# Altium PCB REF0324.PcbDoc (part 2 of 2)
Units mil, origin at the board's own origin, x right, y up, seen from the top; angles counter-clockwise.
Board outline 2010 x 1686 mil, 4 copper layers (Top Layer, Signal Layer 1, Signal Layer 2, Bottom Layer), stack 61.2 mil thick; 109 components, 70 nets, 426 pads, 300 vias.
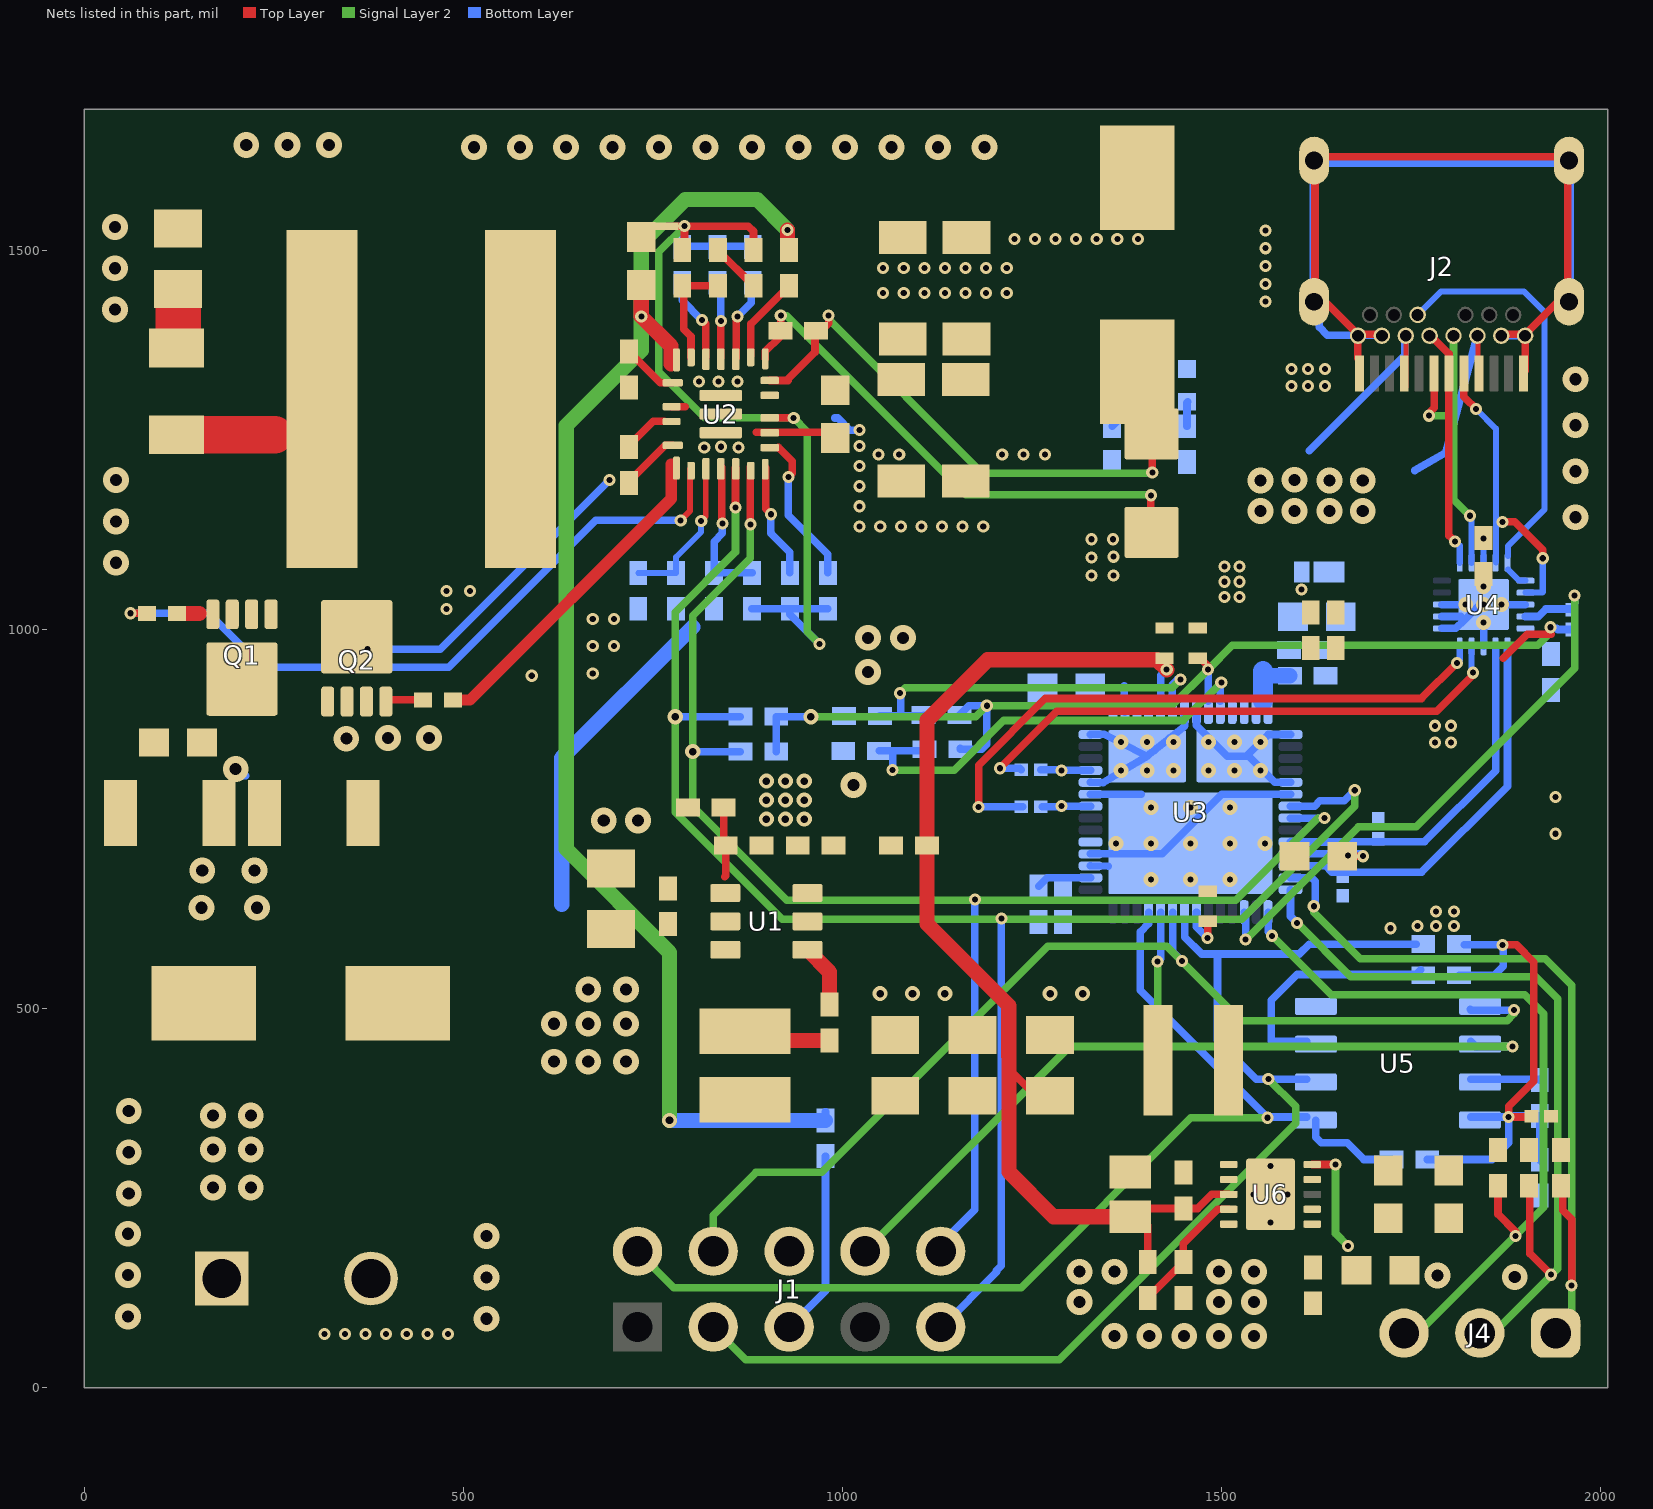
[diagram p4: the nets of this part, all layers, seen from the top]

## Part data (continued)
R20: library part CMP-0025950-3, "RES, 100 k, 1%, 0.063 W, AEC-Q200 Grade 0, 0402", Manufacturer=Vishay-Dale, Power_W=63mW, Supplier Part Number 1=541-100KLCT-ND, TempCo="100 ppm/C", Tolerance_%=1%, Value2=0.063W, Value_Code=133k
R21: library part CMP-0026178-2, "RES, 22.1 k, 1%, 0.063 W, AEC-Q200 Grade 0, 0402", Manufacturer=Vishay-Dale, Power_W=63mW, Supplier Part Number 1=541-22.1KLCT-ND, TempCo="100 ppm/C", Tolerance_%=1%, Value2=0.063W, Value_Code=22k1, ValueDisplayed=22.1k
R22 R23: library part CMP-0026339-2, "RES, 3.83 k, 1%, 0.063 W, AEC-Q200 Grade 0, 0402", Manufacturer=Vishay-Dale, Power_W=63mW, Supplier Part Number 1=541-3.83KLCT-ND, TempCo="100 ppm/C", Tolerance_%=1%, Value2=0.063W, Value_Code=3k83, ValueDisplayed=3.83k
R24 R31 R32: library part CMP-0027008-4, "RES, 0, 5%, 0.05 W, 0201", Manufacturer=Vishay-Dale, Power_W=50mW, Supplier Part Number 1=72M6743, TempCo=ppm/C, Tolerance_%=5%, Value2=0.05W, Value_Code=0000, ValueDisplayed=0
R25: library part CMP-0025950-3, "RES, 100 k, 1%, 0.063 W, AEC-Q200 Grade 0, 0402", Manufacturer=Vishay-Dale, Power_W=63mW, Supplier Part Number 1=541-100KLCT-ND, TempCo="100 ppm/C", Tolerance_%=1%, Value2=0.063W, Value_Code=220k
R26 R37 R38 R46: library part CMP-0026658-1, "RES, 10.0 k, 1%, 0.1 W, 0402", Manufacturer=Panasonic, Power_W=100mW, Supplier Part Number 1=P10.0KLCT-ND, TempCo="100 ppm/C", Tolerance_%=1%, Value2=0.1W, Value_Code=10k0, ValueDisplayed=10.0k
R27: library part CMP-0026359-2, "RES, 3.48, 1%, 0.063 W, AEC-Q200 Grade 0, 0402", Manufacturer=Vishay-Dale, Power_W=63mW, Supplier Part Number 1=541-3.48LLCT-ND, TempCo="100 ppm/C", Tolerance_%=1%, Value2=0.063W, Value_Code=3R48, ValueDisplayed=3.48
R28 R34 R40 R41: library part CMP-0025950-3, "RES, 100 k, 1%, 0.063 W, AEC-Q200 Grade 0, 0402", Manufacturer=Vishay-Dale, Power_W=63mW, Supplier Part Number 1=541-100KLCT-ND, TempCo="100 ppm/C", Tolerance_%=1%, Value2=0.063W, Value_Code=100k
R35: library part CMP-0027184-1, "RES, 100 k, 5%, 0.05 W, 0201", Manufacturer="Yageo America", Power_W=50mW, Supplier Part Number 1=603-RC0201JR-7D100KL, TempCo="200 ppm/C", Tolerance_%=5%, Value2=0.05W, Value_Code=100k
R48 R49 R50 R51: library part CMP-0026918-5, "RES, 3.3 k, 5%, 0.063 W, AEC-Q200 Grade 0, 0402", Manufacturer=Vishay-Dale, Power_W=63mW, Supplier Part Number 1=541-3.3KJCT-ND, TempCo="200 ppm/C", Tolerance_%=5%, Value2=0.063W, Value_Code=3k30, ValueDisplayed=3.3k
U1: library part CMP-0065101-3, "4V to 36 V 0.6 A Synchronous Step-Down Converter, DBV0006A (SOT-23-6)", Alternate Manufacturer="Texas Instruments", Alternate PartNumber=TPS560430YDBVT
U2: library part CMP-0085347-3, "36-V, 16-A Buck-Boost Converter, RPM0026A (VQFN-HR-26)", Alternate Manufacturer="Texas Instruments"
U3: library part CMP-0081032-2, "USB Type-C and USB PD Controller with Integrated Power Switches, RSH0056E (VQFN-56)", Alternate Manufacturer="Texas Instruments", Alternate PartNumber=TPS65987DDHRSHT
U4: library part CMP-0081565-1, "USB Type-C Port Protector: Short-to-VBUS Overvoltage and IEC ESD Protection, RUK0020B (WQFN-20)", Alternate Manufacturer="Texas Instruments"
U5: library part CMP-0078948-1, "8Mb, 86MHz, NOR Flash, SOP-8", Manufacturer="Macronix International Co., LTD", Supplier Part Number 1=1092-1117-ND
U6: library part CMP-0034518-5, "Integrated USB Power Switch with Boost Converter, DRC0010J (VSON-10)", Continuous Current(Max)(A)=1.4, Current Limit(A)="0.13 to 1.4", Current Limit Topology=Constant-Current, Manufacturer="Texas Instruments", Operating Temperature Range="-40 to 85 C", Rating=0

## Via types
v1: diameter 16, hole 8, Top Layer to Bottom Layer, tented both sides, 164 vias
v2: diameter 34, hole 16, Top Layer to Bottom Layer, tented both sides, 84 vias
v3: diameter 19.68, hole 7.87, Top Layer to Bottom Layer, 34 vias
v4: diameter 20, hole 10, Top Layer to Bottom Layer, tented both sides, 18 vias

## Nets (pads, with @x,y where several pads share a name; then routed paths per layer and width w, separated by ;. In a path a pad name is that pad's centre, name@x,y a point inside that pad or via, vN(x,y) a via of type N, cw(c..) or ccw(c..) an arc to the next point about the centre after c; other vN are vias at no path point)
/FLT_TPD: R35.1 U3.31 U4.9 | length 795.5
  Signal Layer 2 w10: v1@1530,593 v1(1532,591) 1681,740 1757,740 1966,949 v1(1966,1045)
  Bottom Layer w10: U3.31@1530.24,627.22 1530,626.98 1532,624.98 1530,622.98 1532,620.98 v1(1532,591) ; U4.9@1901.12,1017.13 1918.13,1017.13 1928,1027 1960.99,1027 R35.1@1962,1025.99 ; R35.1@1966,1034.8 v1(1966,1045)
ADCIN1: R37.1 R40.2 U3.6 | length 499
  Signal Layer 2 w10: v1(1076,916) 1083.02,923.02 1435.02,923.02 v1(1446,934)
  Bottom Layer w10: R40.2@1049.62,886 1077,886 ; v1@1077,914 1077,886 ; R37.1@1107.38,887 1106.38,886 1077,886 ; U3.6@1435.39,905.35 1435.39,927.39 1442,934 v1(1446,934)
ADCIN2: R38.1 R41.2 U3.10 | length 594.2
  Signal Layer 2 w10: v1(1066.5,814.5) 1147.5,814.5 1213,880 1450,880 v1(1500,930)
  Bottom Layer w10: R41.2@1048.62,840 1070,840 ; v1(1066.5,814.5) 1066.5,836.5 1070,840 ; R38.1@1108.38,842 1106.38,840 1070,840 ; U3.10@1498.39,905.35 1498.39,928.39 v1(1500,930)
AGND: C18.2 C19.2 C20.2 NT1.2 R7.1 R14.1 R15.1 R16.1 R17.1 U2.10 | length 1212.7
  Top Layer w10: NT1.2@769,1532 v1(792,1532) ; C18.2@789,1500.62 792,1503.62 v1(792,1532) ; C20.2@883,1500.62 883,1525 876,1532 v1(792,1532) ; U2.10@898,1279.04 v1(936,1279.04)
  Signal Layer 2 w10: v1(792,1532) 758,1498 758,1340 818.96,1279.04 v1(936,1279.04) 954,1261.04 954,997 v1(970,981)
  Bottom Layer w10: R17.1@791,1504.62 R17.1@791,1505.24 ; v1(792,1532) 791,1531 R17.1@791,1505.24 ; R15.1@880,1505.24 R17.1@791,1505.24 ; R7.1@881,1027.38 C19.2@931,1027.38 ; v1(970,981) 931,1020 C19.2@931,1027.38 ; R14.1@981,1027.38 C19.2@931,1027.38
C_CC1: J2.A5 U4.4 U4.7 | length 425.1
  Top Layer w10: J2.A5@1819.95,1339.69 1819.95,1306.98 v1@1838,1288.93 ; v1(1871,1142) 1887,1142 1924,1105 v1(1924,1094)
  Bottom Layer w8: v1(1835.93,1291) 1862.05,1264.88 U4.4@1862.05,1088.3 ; U4.7@1901.12,1048.63 1923.37,1048.63 ; 1924,1049.26 v1(1924,1094)
  Bottom Layer w10: v1@1864,1142 v1(1871,1142)
C_CC2: J2.B5 U4.5 U4.6 | length 561.6
  Bottom Layer w8: J2.B5@1759,1415 1790,1446 1899,1446 1926,1419 1926,1158 1878,1110 U4.5@1878,1097 ; U4.5@1878.5,1079 1893.12,1064.38 U4.6@1901.12,1064.38
C_USB_N: J2.A7 J2.B7 U4.2 | length 413.2
  Top Layer w10: v1(1774,1282) 1774,1286 1780.65,1292.65 J2.A7@1780.65,1337.84
  Signal Layer 2 w10: v1(1774,1282) 1806.24,1282 1806.24,1295 ; J2.B7@1806.24,1387.44 1806.24,1295 ; v1(1828,1150) 1806.24,1171.76 1806.24,1295
  Bottom Layer w8: v1(1828,1150) 1830.25,1147.75 U4.2@1830.25,1088
C_USB_P: J2.A6 J2.B6 U4.1 | length 323.6
  Top Layer w10: J2.B6@1774.75,1387.44 1776.52,1387.44 1800,1363.97 ; J2.A6@1800.53,1349.39 1800.53,1363.43 1800,1363.97 ; v1(1808,1116) 1800,1124 1800,1363.97
  Bottom Layer w8: U4.1@1814.5,1088 1814.5,1110.5
CC1: C36.1 U3.24 U4.12 | length 473.3
  Bottom Layer w10: U3.24@1591.27,719.74 1657,719.74 ; 1657,720 1768,720 1861.75,813.75 U4.12@1861.75,977.76
CC2: C37.1 U3.26 U4.11 | length 520.9
  Bottom Layer w10: U3.26@1591.27,688.24 1637.75,688.24 1645.99,680 1764,680 1877.5,793.5 U4.11@1877.5,977.76
DRAIN1: U3.8 U3.15 U3.19 U3.58@1517.45,832.93 | length 242.3
  Bottom Layer w10: U3.8@1467.25,891 1467.25,873.75 1508.07,832.93 1536.07,832.93 1570.52,798.48 U3.19@1591.27,798.48 ; U3.58@1533.2,832.93 1561.74,861.47 U3.15@1591.27,861.47
  other v3: 1483,814.23 1517.45,814.23 1551.9,814.23 1483,851.63 1517.45,851.63 1551.9,851.63
DRAIN2: U3.7 U3.52 U3.56 U3.57@1402.29,832.93 | length 248.1
  Bottom Layer w10: U3.52@1327.49,798.48 1344,798 1368.7,812.8 U3.57@1402.29,832.93 ; U3.56@1327.49,861.47 1345,862 1367.35,850.66 U3.57@1402.29,832.93 ; U3.7@1451.5,891 1452,873 1432.31,857.13 1411.43,840.3 U3.57@1402.29,832.93
  other v3: 1367.84,814.23 1402.29,814.23 1436.74,814.23 1367.84,851.63 1402.29,851.63 1436.74,851.63
GND: C1.2 C2.2 C3.2 C4.2 C5.2 C6.2 C9.2 C10.2 C12.2 C13.2 C14.2 C15.2 C16.2 C17.2 C21.2 C22.2 C23.2 C25.2 C26.2 C27.2 C28.2 C29.2 C30.2 C32.2 C33.2 C34.2 C35.2 C36.2 C37.2 C38.2 C39.2 C40.2 C41.2 C42.2 C43.2 C44.2 C45.2 C46.2 C47.2 D1.2 D3.2 J1.6 J2.A1 J2.A12 J2.B1 J2.B12 J2.M1 J2.M2 J2.S1 J2.S2 J2.S3 J2.S4 J3.2 NT1.1 Q2.1 Q2.2 Q2.3 R5.1 R20.1 R21.1 R27.1 R28.1 R34.1 R40.1 R41.1 U1.2 U2.9 U2.24 U3.20 U3.45 U3.46 U3.47 U3.51 U3.59@1459.38,717.77 U4.8 U4.13 U4.16 U4.17 U4.18 U4.21@1846,1032.88 U5.4 U6.2 U6.5 U6.11 | length 2557.6
  Top Layer w10: 887,1260 983.5,1260 C12.2@991,1252.5 ; J2.S3@1623.53,1623.94 1623.53,1437.72 1631.76,1437.72 J2.B1@1680.19,1389.29 ; J2.S3@1629.99,1623.78 J2.S2@1948.53,1623.78 ; J2.A12@1680.19,1357.8 J2.B1@1680.19,1389.29 ; J2.M1@1711.68,1389.29 J2.B1@1680.19,1389.29 ; J2.M2@1869.16,1389.29 J2.B12@1900.66,1389.29 ; J2.A1@1898.69,1339.69 1900.66,1341.65 J2.B12@1900.66,1389.29 ; J2.S2@1956.92,1618.94 J2.S1@1956.92,1434.17 ; J2.S1@1958.53,1434.17 J2.S1@1956.92,1434.17 ; J2.B12@1900.66,1389.29 1945.54,1434.17 J2.S1@1956.92,1434.17
  Bottom Layer w10: 990,1279 994,1279 1010,1263 v1(1023,1263) ; U3.45@1327.49,688.24 1351,688 ; U3.46@1327.49,703.99 1422.02,704.02 1500.73,782.73 U3.20@1591.27,782.73 ; U3.51@1327.49,782.73 U3.59@1394.42,782.73 ; J2.S4@1621,1428.78 1621,1615 1960,1615 J2.S1@1960,1428.78 ; J2.S4@1629,1411 1629,1399 1640,1388 J2.M1@1711.76,1388 ; U4.16@1790.88,1001.39 1809.39,1001.39 U4.21@1820.5,1012.5 ; U4.17@1790.88,1017.13 1815.87,1017.13 U4.21@1820.5,1012.5 ; U4.18@1790.88,1032.88 v3(1822.38,1032.88) ; U4.13@1846,977.76 v3(1846,1009.26) ; v3(1846,1032.88) 1840.88,1032.88 U4.21@1820.5,1012.5 ; J2.M2@1869.24,1387.44 J2.B12@1900.73,1387.44 ; v3(1869.62,1032.88) U4.8@1901.12,1032.88
  other v1: 317,71 344.17,71 371.33,71 398.5,71 425.67,71 452.83,71 480,71 1723,606 1941,730.65 1941,779 1782,851 1803,851 1782,873 1803,873 590.5,939 671,942 671,978 699,978 671,1014 699,1014 478,1027 478,1051 509,1051 1023,1136 1050.17,1136 1077.33,1136 1104.5,1136 1131.67,1136 1158.83,1136 1186,1136 1023,1162.5 1023,1189 1023,1215.5 1048,1231 1075.17,1231 1211,1231 1239.25,1231 1267.5,1231 818,1240 863,1240 840,1241 1023,1242 1592.53,1321.39 1614.53,1321.39 1636.53,1321.39 1592.53,1343.39 1614.53,1343.39 1636.53,1343.39 1558.53,1432.39 1054,1444 1081.17,1444 1108.33,1444 1135.5,1444 1162.67,1444 1189.83,1444 1217,1444 1558.53,1455.89 1054,1477 1081.17,1477 1108.33,1477 1135.5,1477 1162.67,1477 1189.83,1477 1217,1477 1558.53,1479.39 1558.53,1502.89 1227,1515 1254.17,1515 1281.33,1515 1308.5,1515 1335.67,1515 1362.83,1515 1390,1515 1558.53,1526.39
  other v2: 1359,68 1405,68 1451,68 1497,68 1543,68 531,91 58,94 1313,113 1497,113 1543,113 531,145.5 1887,146 1785,148 58,148.5 1313,153 1359,153 1497,153 1543,153 531,200 58,203 59,256 59,310.5 59,365 685.5,748 730.5,748 1015,795 346,856 401,857 455,857 1034,944 1034,989 1080,989 42,1088 42,1142.5 1967,1148 42,1197 1967,1208.67 1967,1269.33 1967,1330 41,1422 41,1476.5 41,1531 514.5,1636 575.17,1636 635.83,1636 697.13,1636 758.43,1636 819.72,1636 881.02,1636 942.31,1636 1003.61,1636 1064.91,1636 1126.2,1636 1187.5,1636 214,1639 268.5,1639 323,1639
  other v3: 1564.88,217.6 1542.24,255 1587.52,255 1564.88,292.4 1407.41,670.53 1459.38,670.53 1511.35,670.53 1360.95,717.77 1407.41,717.77 1459.38,717.77 1511.35,717.77 1557.8,717.77 1407.41,765.02 1459.38,765.02 1511.35,765.02 1846,1009.26 1846,1056.5 1846,1056.5
  other v4: 1050,519.7 1092.75,519.7 1135.5,519.7 1274.25,519.7 1317,519.7 900,750 925,750 950,750 900,775 925,775 950,775 900,800 925,800 950,800
I2C1_IRQ: J4.3 R26.1 U3.29 | length 1015.7
  Top Layer w10: R26.1@1865,264.38 1865,229 1888,206 v1(1888,200)
  Signal Layer 2 w10: v1(1567,596) 1645,518 1900,518 1925,493 1925,238 1759,72 J4.3@1741,72
  Bottom Layer w10: U3.29@1561.74,627.22 1561.74,601.26 v1(1567,596)
I2C1_SCL: J4.1 R22.1 U3.27 | length 1062.6
  Top Layer w10: R22.1@1950.29,254.66 1950.29,234 1962,222.29 v1(1962,135)
  Signal Layer 2 w10: v1(1622,635) 1622,627 1683,566 1927,566 1962,531 1962,139 1959.29,136.29 1960.57,135 v1(1962,135) 1962,94.43 1959.29,91.71 1969,82 J4.1@1951,64
  Bottom Layer w10: U3.27@1591.27,672.5 1619.5,672.5 1624,668 v1@1624,635
I2C1_SDA: J4.2 R23.1 U3.28 | length 1056
  Top Layer w10: R23.1@1907,266.38 1907,177 v1(1935,149)
  Signal Layer 2 w10: v1(1600,613) 1671,542 1915,542 1944,513 1944,157 1859,72 J4.2@1841,72
  Bottom Layer w10: U3.28@1591.27,656.75 1591.27,621.73 v1(1600,613)
I2C3_SCL: J1.9 R9.1 U2.5 U3.21 | length 2277.2
  Top Layer w10: v1(859.22,1160.71) U2.5@859.22,1213.05
  Signal Layer 2 w10: v1(859.22,1160.71) 859.22,1102.22 779.85,1022.85 v4(779.85,885) 779.85,758.9 920.75,618 1527,618 1676,767 v1(1676,788)
  Bottom Layer w10: v4(779.85,885) R9.1@865.76,885 ; J1.9@1130,80 1131,80 1204,153 1203,154 1210,161 v1(1210,619) ; U3.21@1591.27,766.98 1622.98,766.98 1630,774 1662,774 v1(1676,788)
I2C3_SDA: J1.10 R10.1 U2.6 U3.22 | length 1998.9
  Top Layer w10: v1(878.9,1138.76) U2.6@878.9,1214.59
  Signal Layer 2 w10: v4@801.88,838 v4(802.88,839) ; v4@803,838 803,767 927,643 1519,643 1627.24,751.24 v1(1636,751.24) ; v4@803,839 803,1018 878.9,1093.9 v1(878.9,1138.76)
  Bottom Layer w10: v4(802.88,839) R10.1@865.76,839 ; J1.10@1130,180 1130,190 1175,235 v1(1175,644) ; U3.22@1591.27,751.24 v1(1636,751.24)
LDO_3V3: C39.1 C45.1 R9.2 R10.2 R22.2 R23.2 R24.1 R26.2 R35.2 R37.2 R38.2 U3.9 U4.10 | length 1411.1
  Top Layer w10: C45.1@1470.5,963.5 1482.64,951.36 v1(1482.64,947.24) ; 1872,962 1903.62,993.62 1935,993.62
  Signal Layer 2 w10: v4(958.74,885) 1176.29,885 v1(1190.71,899.42) 1434.81,899.42 v1(1482.64,947.24) 1514.39,979 1917.16,979 1934,995.84 v1(1934,1003)
  Bottom Layer w10: R10.2@913,839 R9.2@913,885 v4(958.74,885) ; R37.2@1154.62,887 1167.04,899.42 v1(1190.71,899.42) 1190.71,848.71 1184,842 R38.2@1155.62,842 R38.2@1155.62,843.38 ; U3.9@1482.64,905.35 v1(1482.64,947.24) ; 1942.16,1001.84 1943.99,1000.01 R35.2@1962,1000.01
NetC5_1: C5.1 R1.1 | length 58
  Top Layer w60: R1.1@124,1385 C5.1@124,1443
NetC6_1: C6.1 R34.2 U3.44 | length 73.1
  Bottom Layer w10: R34.2@1259,661.24 1270.25,672.5 U3.44@1327.49,672.5
NetC7_1: C7.1 U2.22 | length 51.4
  Top Layer w10: C7.1@724.5,1248.5 750.74,1274.74 U2.22@765.04,1274.74
NetC7_2: C7.2 L1.1 Q1.1 Q1.2 Q1.3 Q2.5 Q2.6 Q2.7 Q2.8 Q2.9@359.67,990.38 R1.2 U2.23 | length 628.9
  Top Layer w10: 251.09,1256.91 262,1246 ; C7.2@722,1198 766.82,1242.82 U2.23@776.48,1242.82
  Top Layer w50: R1.2@122,1256.91 251.09,1256.91
  Bottom Layer w10: v1(374,974) 470,974 v1(693,1197)
NetC8_1: C8.1 U2.20 | length 74.5
  Top Layer w10: C8.1@719,1366.62 760.13,1325.5 U2.20@776.48,1325.5
NetC8_2: C8.2 L1.2 U2.21 U2.25 | length 18
  Top Layer w10: U2.21@775,1294 793,1294
NetC9_1: C9.1 R6.1 U2.3 | length 205.6
  Top Layer w7.87: v1(814,1143) 820,1149 U2.3@820,1214.05
  Bottom Layer w7.87: C9.1@731,1074.62 R6.1@781,1074.62 781,1095.56 814,1128.56 v1(814,1143)
NetC10_1: C10.1 C11.1 C12.1 C13.1 C14.1 C15.1 C16.1 R8.1 U2.11 U2.12 U2.26 | length 700.9
  Top Layer w10: U2.12@904.43,1328.45 928.45,1328.45 929,1329 929,1330.86 964.07,1365.93 964.07,1385.93 982,1403.86 v1(982,1414) ; R8.1@1407.16,1260.73 1409,1258.89 v1(1409,1207)
  Signal Layer 2 w10: v1(982,1414) 982,1408.93 1184.93,1206 v1@1407.53,1206
  other v1: 811.35,1327 836.63,1327 861.91,1327
NetC18_1: C18.1 R12.2 U2.18 | length 146.2
  Top Layer w10: U2.18@800.59,1358.96 800.59,1386.41 791,1396 791,1451.38 C18.1@789,1453.38 R12.2@836,1453.38
NetC19_1: C19.1 U2.7 | length 152.2
  Top Layer w10: U2.7@899,1213.56 899,1159 v1(906,1152)
  Bottom Layer w10: v1(906,1152) 906,1127 907,1126 907,1125.93 931,1101.93 C19.1@931,1074.62
NetC20_1: C20.1 R12.1 | length 66.7
  Top Layer w10: R12.1@836,1500.62 836,1500.38 C20.1@883,1453.38
NetC24_1: C24.1 U1.1 | length 84.4
  Top Layer w20: U1.1@954.13,577.6 983.37,548.37 C24.1@983.37,505.26
NetC24_2: C24.2 L2.1 U1.6 | length 116.4
  Top Layer w20: L2.1@871.92,470.08 883.98,458.02 C24.2@983.37,458.02
NetC27_1: C27.1 U3.35 | length 62.3
  Top Layer w10: v1(1482,593) C27.1@1482,615
  Bottom Layer w10: U3.35@1467.25,627.22 1467.25,607.75 v1(1482,593)
NetC28_1: C28.1 U6.7 U6.10 | length 144.8
  Top Layer w10: U6.10@1620,294.37 1650.27,294.37 v1@1650.64,294
  Signal Layer 2 w10: v1(1650.64,294.24) 1650.64,203.36 v1(1667,187)
NetC31_2: C31.2 R27.2 | length 45.9
  Bottom Layer w10: R27.2@1356,1268.14 C31.2@1388.43,1300.56
NetC40_1: C40.1 U4.3 | length 32
  Bottom Layer w8: U4.3@1846,1088 v1(1846,1120)
NetC43_1: C43.1 R24.2 R48.2 R49.2 R50.2 R51.2 U5.8 | length 744.8
  Top Layer w10: v1(1871,584) 1889.35,584 1912,561.35 1912,404 1878.92,370.92 v1(1878.92,357) 1908.01,357 R24.2@1909.01,358
  Bottom Layer w10: R48.2@1771.62,301 1857,301 1878.92,322.92 v1(1878.92,357) ; R51.2@1813.62,544 1860,544 1872,556 1872,583 v1(1871,584) R49.2@1820.62,584 ; U5.8@1829.27,357 v1(1878.92,357) ; C43.1@1921,299.62 C43.1@1920,300.62 R50.2@1920,358.38 1877.54,358.38 v1(1878.92,357)
NetD3_1: D3.1 R46.1 | length 32.7
  Bottom Layer w10: R46.1@1454.75,1268.14 1454.75,1299.1 D3.1@1456,1300.35
NetJ1_5: J1.5 R13.1 | length 245.3
  Bottom Layer w10: J1.5@930,80 978,128 R13.1@978,305.38
NetL3_2: L3.2 U6.1
NetQ1_4: Q1.4 R3.2 | length 29.3
  Top Layer w20: R3.2@122.69,1021 152,1021
NetQ2_4: Q2.4 R4.2 | length 56
  Top Layer w10: Q2.4@398.06,904.94 400.45,907.34 R4.2@447,907.34 ; R4.2@447,907.31 R4.2@447.31,907 ; R4.2@447.31,907.34 R4.2@452.9,907.34
NetR2_1: R2.1 R7.2 U2.4 | length 194.4
  Top Layer w10: U2.4@841,1214.05 841,1141 v1(842,1140)
  Bottom Layer w10: v1(842,1140) 842,1127 831,1116 R2.1@831,1074.62 R7.2@881,1074.62
NetR3_1: R3.1 U2.2 | length 933.3
  Top Layer w7.87: v1(787,1144) 799,1156 U2.2@799,1211.59
  Top Layer w10: v1(61.53,1021.39) R3.1@86.85,1021.39
  Bottom Layer w10: v1(61.53,1021.39) 164.61,1021.39 236,950 481,950 675,1144 v1(787,1144)
NetR4_1: R4.1 U2.1 | length 443.5
  Top Layer w15: R4.1@486.69,907 509,907 774.51,1172.51 774.51,1218.21
NetR5_2: R5.2 U6.6
NetR11_2: R11.2 U2.14 | length 113.1
  Top Layer w10: U2.14@879.53,1361.2 879.53,1402.91 R11.2@930,1453.38
NetR14_2: R14.2 U2.8 | length 196.4
  Top Layer w10: U2.8@916,1240 934,1222 934,1206 v1(929,1201)
  Bottom Layer w10: v1(929,1201) 929,1150.93 981,1098.93 R14.2@981,1074.62
NetR15_2: R15.2 U2.15 | length 107.8
  Top Layer w10: U2.15@860,1358.74 860,1411 v1(862,1413)
  Bottom Layer w10: v1(862,1413) 880,1431 880,1455.38 R15.2@882,1457.38
NetR16_2: R16.2 U2.16 | length 85.3
  Top Layer w10: U2.16@840,1358.74 v1(840,1407)
  Bottom Layer w10: v1(840,1407) R16.2@840,1444
NetR17_2: R17.2 U2.17 | length 110.9
  Top Layer w10: v1(815,1408) 820,1403 U2.17@820,1359.34
  Bottom Layer w10: R17.2@789,1457.38 789,1434 v1(815,1408)
NetR18_1: R18.1 R20.2 U1.4 | length 87.7
  Top Layer w10: R18.1@843.62,760 843.62,717.76 R20.2@846.38,715 846.38,675.38 845,674
NetR19_1: R19.1 R21.2 U1.3
NetR25_1: R25.1 R28.2 U6.4 | length 169.6
  Top Layer w10: R25.1@1403,118.38 1450,165.38 R28.2@1450,165.62 1450,190 1495.32,235.32 U6.4@1509.76,235.32
NetR31_2: R31.2 U3.50 | length 63.9
  Bottom Layer w10: R31.2@1263.99,766 1288.03,766 v1(1289.02,766.98) U3.50@1327.49,766.98
NetR32_2: R32.2 U3.53 | length 66
  Bottom Layer w10: R32.2@1261.99,815 1288,815 v1(1289,814) 1289.23,814.23 U3.53@1327.49,814.23
NetR50_1: R50.1 U5.7 | length 91.3
  Bottom Layer w10: U5.7@1829.27,407 1918.62,407 R50.1@1920,405.62
NetR51_1: R51.1 U5.3 | length 314.3
  Bottom Layer w10: U5.3@1612.73,457 1566,457 1566,511 1600,545 1757,545 R51.1@1763,551
P_3V3: C22.1 C25.1 C26.1 C42.1 C46.1 C47.1 L2.2 L3.1 R19.2 R25.2 U3.5 U6.3 | length 1478.7
  Top Layer w10: 1220,420 C46.1@1264.47,375.53 ; C25.1@1380,236.38 C26.1@1450,236.38 1469.02,236.38 1487.64,255 U6.3@1509.76,255 ; R25.2@1403,165.62 C25.1@1403,214
  Top Layer w20: C25.1@1380,225.47 1278.89,225.47 1220,284.36 1220,420 1219.75,450 1219.75,503.79 1111.62,611.92 R19.2@1111.62,715 1111.62,880.2 1191.42,960 1415,960 v1(1428,947)
  Bottom Layer w10: U3.5@1420.39,900 1420.39,939.39 v1(1428,947)
P_5V: C29.1 C30.1 C38.1 U3.25 U6.9 | length 125.9
  Top Layer w10: C38.1@1659.5,701 v1(1687,701)
  Bottom Layer w10: U3.25@1591.27,703.99 1684.01,703.99 v1(1687,701) ; v1@1806,608 v1(1807,609)
  other v1: 1759,609 1783,609 1783,628 1807,628 1667,702
PP_HV: C11.2 C44.1 R8.2 U2.13 U3.1 U3.2 U3.11 U3.12 | length 715.2
  Top Layer w10: U2.13@898.52,1356.99 898.52,1366.9 C11.2@917.31,1385.69 ; C11.2@918.38,1394 919,1394.62 v1(919,1414) ; R8.2@1407.16,1139.81 v1(1407.16,1177)
  Signal Layer 2 w10: v1(919,1414) 926.93,1414 1162.93,1178 v1@1407.53,1178
  Bottom Layer w10: 1372,926 U3.2@1372.76,891
  other v1: 1504,1043 1524,1043 1504,1063 1524,1063 1329,1071 1358,1071 1504,1083 1524,1083 1329,1095 1358,1096 1329,1119 1357,1119
SPI_CLK: J1.8 U3.38 U5.6 | length 1205.2
  Signal Layer 2 w10: J1.8@1030,180 1300,450 v1(1884,450) ; 1416,456 v1(1416,562)
  Bottom Layer w10: J1.8@1030,180 J1.8@1038,180 ; v1(1416,562) 1420.01,566.01 U3.38@1420.01,627.22 ; U5.6@1829.27,457 1837.27,449 1838.27,450 v1(1884,450)
SPI_CSZ: J1.2 R48.1 U3.39 U5.1 | length 1475.8
  Signal Layer 2 w10: J1.2@730,180 778,132 1236,132 1460,356 v1(1561,356)
  Bottom Layer w10: U3.39@1404.26,627.22 1404.26,612.26 1393,601 1393,524 v1(1561,356) 1562,357 U5.1@1612.73,357 ; U5.1@1624.73,353 1624.73,330.27 1632,323 1666,323 1688,301 R48.1@1724.38,301
SPI_MISO: J1.3 R49.1 U3.36 U5.2 | length 1578.7
  Signal Layer 2 w10: J1.3@830,80 873,37 1286,37 1598,349 1598,371 v1(1562,407)
  Bottom Layer w10: U3.36@1452,617 1452,594 1474,572 1603,572 1616,585 R49.1@1757.38,585 ; 1495,567 1495,458 1546,407 v1(1562,407) U5.2@1612.73,407
SPI_MOSI: J1.4 U3.37 U5.5 | length 1427.2
  Signal Layer 2 w10: J1.4@830,180 830,227.68 886.32,284 973.15,284 1271.15,582 1428,582 1526,484 1877,484 1886,493 v1(1886,498)
  Bottom Layer w10: U3.37@1435.76,627.22 1435.76,575.24 v1(1448,563) ; U5.5@1828.27,499 1829.27,498 v1(1886,498)
SYS_PWR: C1.1 C2.1 C3.1 C4.1 C21.1 C23.1 J3.1 Q1.5 Q1.6 Q1.7 Q1.8 Q1.9@208.33,934.62 R2.2 R6.2 R18.2 U1.5 | length 450.4
  Bottom Layer w10: v2@200,807 v2@213,807
  Bottom Layer w20: 630,637.35 630,830.3 802.88,1003.18
  other v2: 170,264 220,264 170,314 220,314 170,359 220,359 620,430 665,430 715,430 620,480 665,480 715,480 665,525 715,525 155,633 228,633 156,682 225,682 200,816
USB_N: R32.1 U4.14 | length 740.7
  Top Layer w10: v1(1208,817) 1283,892 1784,892 v1@1833.5,941.5
  Bottom Layer w8: v1@1830.25,943 U4.14@1830.25,977.76
  Bottom Layer w10: v1(1208,817) 1234.01,817 R32.1@1236.01,815
  other v1: 1832,943
USB_P: R31.1 U4.15 | length 813.2
  Top Layer w10: v1(1180,766) 1180,821 1268,909 1764,909 v1(1811,956)
  Bottom Layer w8: v1@1814.5,959.5 U4.15@1814.5,977.76
  Bottom Layer w10: v1@1185,766 R31.1@1236.01,766 R31.1@1238.01,766
VBUS: C31.1 C32.1 C33.1 C34.1 C35.1 C41.1 D1.1 J2.A4 J2.A9 J2.B4 J2.B9 R46.2 U3.3 U3.4 U3.13 U3.14 | length 611.8
  Top Layer w7.09: J2.A9@1743.53,1320.39 J2.B4@1743.53,1384.29 ; J2.A4@1838.53,1320.39 J2.B9@1838.53,1384.29
  Bottom Layer w10: 1555,945 1561,939 ; 1616,1236 1742,1362 J2.B4@1742,1383.9 ; 1755.12,1209.66 1795.97,1233.11 J2.B9@1837.74,1387.44
  Bottom Layer w20: 1561,939 C32.1@1590.38,939
  Bottom Layer w26.77: 1555,905.98 1555,945
  other v1: 1606,1053
  other v2: 1551.53,1156.39 1596.53,1156.39 1642.53,1156.39 1686.53,1156.39 1551.53,1196.39 1642.53,1196.39 1686.53,1196.39 1596.53,1197.39
VCC: C17.1 R11.1 R13.2 U2.19 | length 1848.4
  Top Layer w20: C17.1@735,1450.5 v1(735,1413) 774,1374 774,1350 ; v1(928,1527) 928,1502.62 R11.1@930,1500.62
  Signal Layer 2 w20: v4(772.23,352.62) 772.23,574.14 636,710.37 636,1269 735,1368 v1(735,1413) 735,1509 793,1567 888,1567 v1(928,1527)
  Bottom Layer w10: R13.2@978,352.62 R13.2@978,364
  Bottom Layer w20: v4(772.23,352.62) R13.2@978,352.62
pads on no net: J1.1 J1.7 J2.A2 J2.A3 J2.A8 J2.A10 J2.A11 J2.B2 J2.B3 J2.B8 J2.B10 J2.B11 Q1. Q1.9@208.33,947.42 Q2. Q2.9@359.67,977.58 U3.16 U3.17 U3.18 U3.23 U3.30 U3.32 U3.33 U3.34 U3.40 U3.41 U3.42 U3.43 U3.48 U3.49 U3.54 U3.55 U3.57@1375.72,832.93 U3.57@1428.87,832.93 U3.58@1490.87,832.93 U3.58@1544.02,832.93 U3.59@1381.43,684.9 U3.59@1381.43,750.65 U3.59@1433.39,684.9 U3.59@1433.39,750.65 U3.59@1485.36,684.9 U3.59@1485.36,750.65 U3.59@1537.33,684.9 U3.59@1537.33,750.65 U4.19 U4.20 U4.21@1827.3,1014.18 U4.21@1827.3,1051.58 U4.21@1864.7,1014.18 U4.21@1864.7,1051.58 U6.8

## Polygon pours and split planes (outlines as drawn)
GND on Top Layer "GND_L01_P332" (solid, remove dead copper, pour order 332): 933,628 1058,628 1111.62,574.38 1111.62,447.46 1097.11,432.95 1030,433.12 1015,448.12 1015,570 982.65,602.35 934,602.35 928.99,607.36 928.99,623.99
NetC10_1 on Top Layer "NETC10_1_L01_P188" (solid, remove dead copper, pour order 188): 877,1332 890,1319 889.94,1296 884,1301.94 840.5,1301.94 809.66,1301.94 800.49,1311.11 800.49,1332
P_3V3 on Top Layer "P_3V3_L01_P128" (solid, remove dead copper, pour order 128): 1392.02,506 1306.02,420 797.84,420 793.1,415.26 793.1,341.45 802.55,332 1425.27,332 1448,354.73 1448,495 1437,506
GND on Top Layer "GND_L01_P330" (solid, remove dead copper, pour order 330): 0,1686 2010,1686 2010,0 0,0
NetC7_2 on Top Layer "NETC7_2_L01_P284" (solid, remove dead copper, pour order 284): 75.58,1292.5 76.09,1292 284,1292 212.97,1220.97 75.58,1221.32
NetC7_2 on Top Layer "NETC7_2_L01_P246" (solid, remove dead copper, pour order 246): 350,1552 361,1541 361,1075 455,1075 455,943 311,943 311,989 297,1003 296,1002 188,1002 188,1063 193,1068 193,1547 198,1552
NetC8_2 on Top Layer "NETC8_2_L01_P298" (solid, remove dead copper, pour order 298): 813.01,1276.99 801.51,1276.99 789.5,1289 745.53,1289 742,1292.53 742,1310 786.8,1310.34 806,1291.15 814,1291.15 814,1277.17
NetC8_2 on Top Layer "NETC8_2_L01_P290" (solid, remove dead copper, pour order 290): 641,1523 650,1409 718,1312 626,1312 626,1523
NetC10_1 on Top Layer "NETC10_1_L01_P310" (solid, remove dead copper, pour order 310): 1373,1281 1373,1225 1317,1281
PP_HV on Top Layer "PP_HV_L01_P264" (solid, remove dead copper, pour order 264): 1428,1131 1475,1097 1428,1097
PP_HV on Top Layer "PP_HV_L01_P238" (solid, remove dead copper, pour order 238): 1312,1161 1383,1161 1383,1026 1312,1026
NetC8_2 on Top Layer "NETC8_2_L01_P254" (solid, remove dead copper, pour order 254): 529,1527 542,1540 627,1540 636,1531 636,1386.38 693,1336.44 731,1336.44 748,1311 787.14,1311 794.12,1304.02 794.98,1304.02 806,1293 814,1293 814,1276 805.84,1284.16 802.84,1284.16 793,1294 788,1289 701.73,1289 623,1080 528,1077.8
SYS_PWR on Top Layer "SYS_PWR_L01_P166" (solid, remove dead copper, pour order 166): 779,776 781,778 811,778 813,776 813,613 796,613 795,614 795,743 782,743 779,746
PP_HV on Top Layer "PP_HV_L01_P018" (solid, remove dead copper, pour order 18): 1312,1107 1537,1107 1537,1026 1312,1026
NetR5_2 on Top Layer "NETR5_2_L01_P118" (solid, remove dead copper, pour order 118): 1609,220 1609,145 1630,145 1635,150 1635,215 1630,220
NetC28_1 on Top Layer "NETC28_1_L01_P116" (solid, remove dead copper, pour order 116): 1610,240 1665,240 1675,230 1675,195 1680,190 1690,180 1700,180 1700,135 1660,135 1655,140 1655,225 1650,230 1610,230
P_5V on Top Layer "P_5V_L01_P114" (solid, remove dead copper, pour order 114): 1610,280 1675,280 1700,305 1820,305 1825,300 1825,270 1820,265 1670,265 1665,270 1610,270
GND on Top Layer "GND_L01_P110" (solid, remove dead copper, pour order 110): 1535,270 1470,270 1460,260 1355,260 1351,264 1351,305 1356,310 1420,310 1435,295 1460,295 1465,290 1465,280 1535,280
NetL3_2 on Top Layer "NETL3_2_L01_P108" (solid, remove dead copper, pour order 108): 1490,512.49 1490,296 1496,290 1522,290 1522,313 1535,326 1535,512.49
SYS_PWR on Top Layer "SYS_PWR_L01_P100" (solid, remove dead copper, pour order 100): 595,630 725,630 740,615 740,405 595,405
NetR19_1 on Top Layer "NETR19_1_L01_P094" (solid, remove dead copper, pour order 94): 1000,727 1054,727 1054,709 985,640 935,640 935,662
NetR18_1 on Top Layer "NETR18_1_L01_P092" (solid, remove dead copper, pour order 92): 825,645 830,640 865,640 865,645 865,650 865,685 825,685
NetC24_2 on Top Layer "NETC24_2_L01_P078" (solid, remove dead copper, pour order 78): 812,440 809.66,442.34 809.66,574.87 824.79,590 870.34,590 880,580.34 933.51,526.83 933.51,440.06
SYS_PWR on Top Layer "SYS_PWR_L01_P074" (solid, remove dead copper, pour order 74): 825,630 830,625 865,625 865,605 830,605 820,595 760,595 735,570 595,570 595,630
P_5V on Top Layer "P_5V_L01_P152" (solid, remove dead copper, pour order 152): 1816,281 1819,294 1819,300 1819,654 1766,654 1745.71,633.71 1742.23,288.52 1751,281 1807,281
DRAIN2 on Top Layer "DRAIN2_L01_P224" (solid, remove dead copper, pour order 224): 1353,863 1451,863 1451,798 1353,798
NetQ1_4 on Top Layer "NETQ1_4_L01_P048" (solid, remove dead copper, pour order 48): 133,1040 178.74,1040 178.74,1000 133,1000
NetC7_2 on Top Layer "NETC7_2_L01_P250" (solid, remove dead copper, pour order 250): 682.49,1207 709.5,1209 709.5,1201 713.5,1197 713.5,1148 707.5,1142 682.49,1142
GND on Top Layer "GND_L01_P258" (solid, remove dead copper, pour order 258): 813,1268 807,1262 807,1235 811,1231 868,1231 872,1235 872,1250 885,1250 890,1255 940.33,1255 944.88,1259.55 967,1237.43 967,1232 969,1230 1019,1230 1019,1272 966,1272 962,1268
VBUS on Top Layer "VBUS_L01_P230" (solid, remove dead copper, pour order 230): 1527,1250.39 1723.53,1250.39 1723.53,1136 1527,1136
VBUS on Top Layer "VBUS_L01_P266" (solid, remove dead copper, pour order 266): 1600.02,1132.02 1607,1139 1724,1139 1724,1006 1597.84,1006
GND on Top Layer "GND_L01_P268" (solid, remove dead copper, pour order 268): 969.02,1272 1305,1272 1305,1206.57 1204.7,1122 971,1122 970,1121
NetC10_1 on Top Layer "NETC10_1_L01_P016" (solid, remove dead copper, pour order 16): 950,1300.33 961.6,1281 1424.53,1281 1424.53,1481.39 1419.53,1476.39 1295.53,1476.39 1295.53,1412 1045.14,1412 950,1316.86
NetC10_1 on Top Layer "NETC10_1_L01_P274" (solid, remove dead copper, pour order 274): 1293,1483 1294,1482 1434,1482 1444,1472 1443,1471 1443,1281 1295,1281 1292,1284
NetC10_1 on Top Layer "NETC10_1_L01_P260" (solid, remove dead copper, pour order 260): 878.9,1319 878.9,1325.55 883.45,1325.55 890,1319 952.14,1319 969.53,1336.39 979.39,1336.39 979.39,1297.39 978,1296 889.94,1296 879.07,1306.87
NetC10_1 on Top Layer "NETC10_1_L01_P288" (solid, remove dead copper, pour order 288): 878.9,1325.55 878.9,1312.77 883.82,1307.85 890,1319
LDO_3V3 on Top Layer "LDO_3V3_L01_P210" (solid, remove dead copper, pour order 210): 1913,1012 1960,1012 1960,298 1857,298 1857,956 1864,963
SYS_PWR on Top Layer "SYS_PWR_L01_P000" (solid, remove dead copper, pour order 0): 260,991 260,61 255,54 134,54 134,991
SYS_PWR on Top Layer "SYS_PWR_L01_P242" (solid, remove dead copper, pour order 242): 85,591 174,591 174,446 171,443 85,443
SYS_PWR on Top Layer "SYS_PWR_L01_P304" (solid, remove dead copper, pour order 304): 85,443 212,443 214,441 214,329
SYS_PWR on Top Layer "SYS_PWR_L01_P306" (solid, remove dead copper, pour order 306): 85,591 165,591 174,600 174,692
DRAIN1 on Top Layer "DRAIN1_L01_P226" (solid, remove dead copper, pour order 226): 1469,865 1567,865 1567,800 1469,800
GND on Top Layer "GND_L01_P324" (solid, remove dead copper, pour order 324): 1352,777 1569,777 1569,658 1352,658
GND on Top Layer "GND_L01_P326" (solid, remove dead copper, pour order 326): 1616,683 1616,720 1568,720 1569,719 1569,683
GND on Bottom Layer "GND_L04_P320" (solid, remove dead copper, pour order 320): 0,1690 2010,1690 2010,0 0,0
SYS_PWR on Bottom Layer "SYS_PWR_L04_P198" (solid, remove dead copper, pour order 198): 768,1039 772,1043 842,1043 846,1039 846,1007 769,1007 768,1008
LDO_3V3 on Bottom Layer "LDO_3V3_L04_P148" (solid, remove dead copper, pour order 148): 1938,1006 1947,997 1947,976 1923,976 1923,987 1921,987 1910,998 1910,1006
PP_HV on Bottom Layer "PP_HV_L04_P030" (solid, remove dead copper, pour order 30): 1495,1092 1535,1092 1535,910.47 1529.88,905.35 1514.13,905.35 1515.24,930.24 1495,959.54
PP_HV on Bottom Layer "PP_HV_L04_P020" (solid, remove dead copper, pour order 20): 1250,1130 1375,1130 1375,950 1250,950
VBUS on Bottom Layer "VBUS_L04_P026" (solid, remove dead copper, pour order 26): 1615,1245 1615,993.58 1559.45,930 1540,930 1540,1245
PP_HV on Bottom Layer "PP_HV_L04_P140" (solid, remove dead copper, pour order 140): 1346.11,899 1378,899 1380,950 1378,959 1361,954 1307.54,951.77
VBUS on Bottom Layer "VBUS_L04_P038" (solid, remove dead copper, pour order 38): 1385,1145 1385,889.61 1410,889.61 1410,955 1471,1016 1471,1145
VBUS on Bottom Layer "VBUS_L04_P044" (solid, remove dead copper, pour order 44): 1390,1210 1435,1210 1435,1115 1425,1105 1390,1105
VBUS on Bottom Layer "VBUS_L04_P142" (solid, remove dead copper, pour order 142): 1640,1245 1640,1267 1746.67,1373.67 1748.98,1357.7 1835.24,1349.92 1790,1196 1729,1115 1649,1115 1644,1120 1640,1116 1433,1116 1430,1119 1426,1115 1379,1115 1379,1245
VBUS on Bottom Layer "VBUS_L04_P144" (solid, remove dead copper, pour order 144): 1634,1256 1647,1256 1650,1253 1650,1234 1627,1234 1626,1233 1622,1237 1622,1244
NetC10_1 on Bottom Layer "NETC10_1_L04_P276" (solid, remove dead copper, pour order 276): 804,1339 875,1339 875,1310 873,1308 804,1308
SYS_PWR on Bottom Layer "SYS_PWR_L04_P218" (solid, remove dead copper, pour order 218): 223.12,920.38 300,843.5 344.88,798.62 482.26,661.24 638.98,661.24 742,558.22 742,386 693,337 471.87,337 235.87,101 124,101 124,920.38
GND on Signal Layer 2 "GND_L03_P314" (solid, remove dead copper, pour order 314): 0,1686 2010,1686 2010,0 0,0
P_5V on Signal Layer 2 "P_5V_L03_P154" (solid, remove dead copper, pour order 154): 1801.5,598.5 1819,603 1819,611 1819,630 1729,720 1670,716 1660,699 1759.96,593.61
SYS_PWR on Signal Layer 2 "SYS_PWR_L03_P244" (solid, remove dead copper, pour order 244): 134,1047 259,1047 259,53 135,53 133,55 134,56
GND on Signal Layer 1 "GND_L02_P194" (solid, remove dead copper, pour order 194): 0,1686 2010,1686 2010,0 0,0

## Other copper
Top Layer:
  pour cut-out: 1868,376 1926,376 1926,347 1923,344 1868,344
  pour cut-out: 1641.64,259.8 1713.2,259.8 1718,255 1696.9,233.9 1684.42,233.9 1668.13,250.2 1641.64,250.2
  pour cut-out: 1300.6,1271.6 1366.51,1214.49 1375,1206 1394.08,1206 1394.08,1198.86 1405.7,1187.24 1403.88,1187.24 1394.42,1177.78 1394.42,1170.49 1389.93,1166 1299.97,1166
  pour cut-out: 1409.2,1186.61 1419.13,1196.54 1419.13,1204.76 1421.21,1206.84 1440.29,1206.84 1440.29,1210.6 1453,1223.31 1453,1169.85 1435.37,1169.85 1420.49,1169.85 1420.49,1177.29 1410.63,1187.15 1406.46,1187.15
  pour cut-out: 1446.5,507 1485,507 1485,358 1474,347 1446.5,347
  pour cut-out: 361,1537 528,1537 528,1077.8 516,1075 515.32,1075 516,1075 361,1075
  pour cut-out: 757.08,1259.45 755.74,1258.11 792.26,1258.11 793.6,1251.06 807.88,1265.34
  pour cut-out: 877.81,1291.74 879.78,1291.74 883.37,1288.15 883.68,1288.15 883.68,1270.75 887.89,1266.54 866.02,1266.54
  pour cut-out: 807.29,1230.65 800,1237.95 800,1236.28 796.25,1232.54 796.25,1231.12

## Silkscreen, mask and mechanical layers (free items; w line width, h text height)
Top Overlay:
  text "PMP40801E1" at 590.5,916 h72.83
Drill Drawing:
  the board outline again, w39.37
